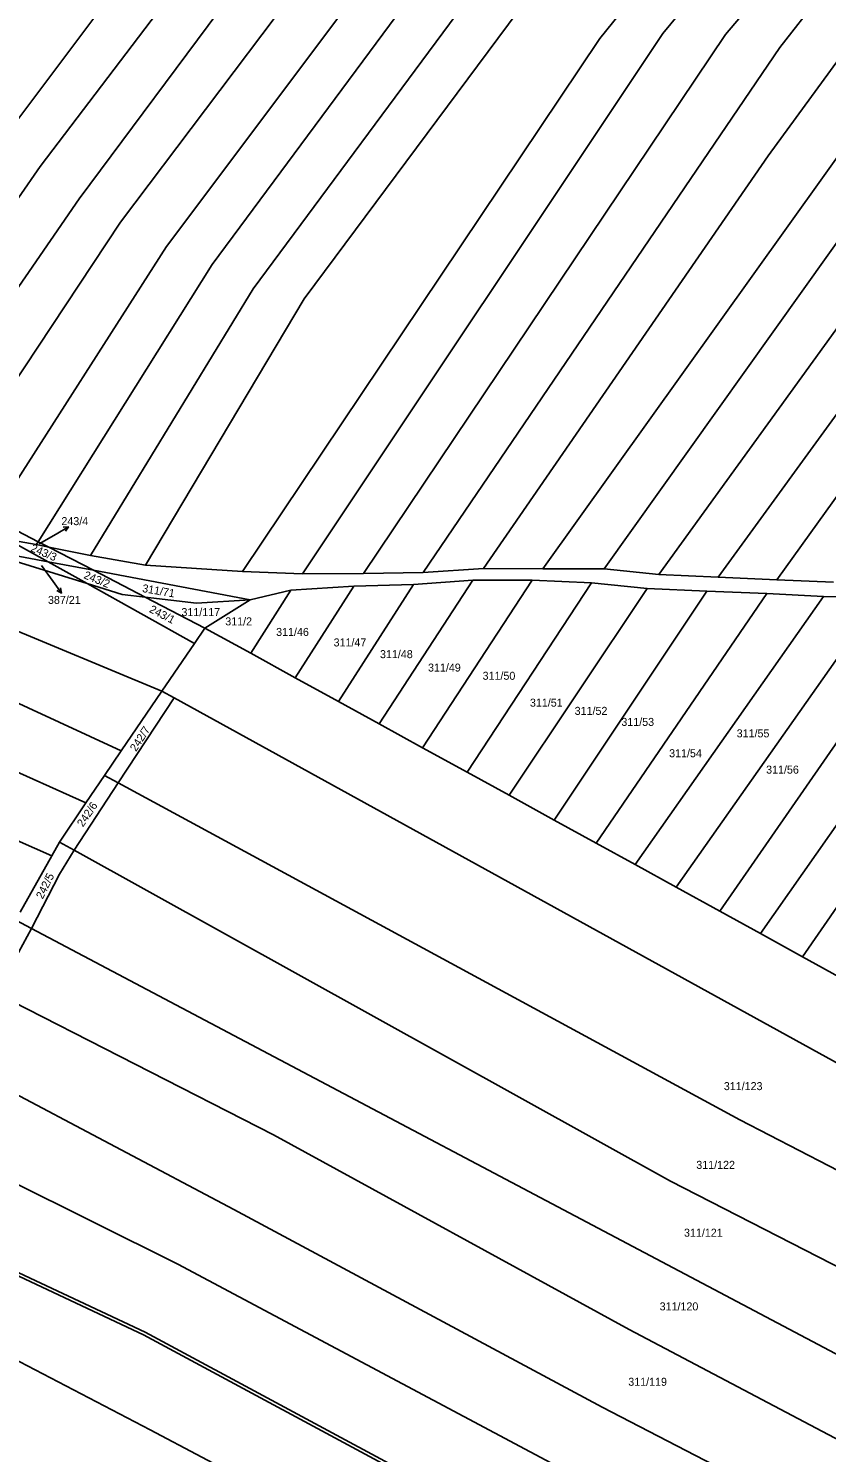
# Model space of a CAD drawing. Extents: x -580630 to -576196, y -1189024 to -1183567.
# Drawn here: x -579840 to -579670.5, y -1186458.9 to -1186156.5 of the extents above; entities that cross this region are included whole.
import ezdxf

# ---------------------------------------------------------------- set-up
doc = ezdxf.new("R2010")
doc.units = 0
for name, color, linetype in [('Vrstva 1', 7, 'Continuous'), ('Vrstva 16', 7, 'Continuous'), ('Vrstva 18', 7, 'Continuous'), ('Vrstva 6', 7, 'Continuous')]:
    doc.layers.add(name, color=color, linetype=linetype)

msp = doc.modelspace()

# ---------------------------------------------------------------- linework, layer by layer
at = {"layer": 'Vrstva 1'}
for p, q in [((-579847.64, -1186260.48), (-579837.97, -1186265.49)), ((-579844.38, -1186265.03), (-579835.86, -1186269.77)), ((-579837.97, -1186265.49), (-579835.72, -1186266.66)), ((-579835.72, -1186266.66), (-579826.23, -1186271.57)), ((-579835.86, -1186269.77), (-579827.55, -1186274.4)), ((-579826.23, -1186271.57), (-579815.23, -1186277.27)), ((-579827.55, -1186274.4), (-579804.76, -1186287.09)), ((-579815.23, -1186277.27), (-579802.55, -1186283.84)), ((-579802.55, -1186283.84), (-579804.76, -1186287.09)), ((-579802.55, -1186283.84), (-579792.82, -1186289.19)), ((-579804.76, -1186287.09), (-579811.7, -1186297.26)), ((-579792.82, -1186289.19), (-579783.36, -1186294.39)), ((-579820.34, -1186309.91), (-579811.7, -1186297.26)), ((-579811.7, -1186297.26), (-579809.11, -1186298.69)), ((-579783.36, -1186294.39), (-579774.18, -1186299.44)), ((-579809.11, -1186298.69), (-579820.97, -1186316.73)), ((-579809.11, -1186298.69), (-579630.91, -1186396.85)), ((-579774.18, -1186299.44), (-579765.52, -1186304.21)), ((-579765.52, -1186304.21), (-579756.35, -1186309.24)), ((-579756.35, -1186309.24), (-579746.87, -1186314.45)), ((-579823.91, -1186315.14), (-579820.34, -1186309.91)), ((-579823.91, -1186315.14), (-579827.82, -1186320.97)), ((-579746.87, -1186314.45), (-579737.97, -1186319.35)), ((-579820.97, -1186316.73), (-579830.35, -1186331.01)), ((-579827.82, -1186320.97), (-579833.42, -1186329.3)), ((-579737.97, -1186319.35), (-579728.36, -1186324.64)), ((-579728.36, -1186324.64), (-579719.49, -1186329.52)), ((-579833.42, -1186329.3), (-579835.05, -1186332.19)), ((-579719.49, -1186329.52), (-579711.2, -1186334.07)), ((-579835.05, -1186332.19), (-579841.79, -1186344.16)), ((-579830.35, -1186331.01), (-579833.41, -1186336.14)), ((-579833.41, -1186336.14), (-579839.4, -1186347.64)), ((-579711.2, -1186334.07), (-579702.5, -1186338.85)), ((-579702.5, -1186338.85), (-579693.22, -1186343.96)), ((-579693.22, -1186343.96), (-579684.59, -1186348.7)), ((-579839.4, -1186347.64), (-579846.88, -1186361.39)), ((-579684.59, -1186348.7), (-579675.63, -1186353.63)), ((-579675.63, -1186353.63), (-579666.49, -1186358.66)), ((-579808.31, -1186418.94), (-579844.26, -1186401)), ((-579851.95, -1186416.9), (-579815.57, -1186433.93)), ((-579815.26, -1186433.34), (-579851.66, -1186416.29)), ((-579705.84, -1186473.49), (-579808.31, -1186418.94)), ((-579814.2, -1186454.11), (-579875.68, -1186422.09)), ((-579713, -1186488.35), (-579815.26, -1186433.34)), ((-579815.57, -1186433.93), (-579713.31, -1186488.94)), ((-579574.05, -1186580.71), (-579814.2, -1186454.11))]:
    msp.add_line(p, q, dxfattribs=at)
at = {"layer": 'Vrstva 16'}
for p, q in [((-579837.73, -1186265.96), (-579834.14, -1186263.87)), ((-579831.549, -1186262.357), (-579834.14, -1186263.87)), ((-579837.29, -1186270.52), (-579834.78, -1186273.97)), ((-579833.019, -1186276.399), (-579834.78, -1186273.97))]:
    msp.add_line(p, q, dxfattribs=at)
for points in [[(-579832.665, -1186262.43), (-579831.549, -1186262.357), (-579832.161, -1186263.293)], [(-579833.201, -1186275.296), (-579833.019, -1186276.399), (-579834.011, -1186275.883)]]:
    msp.add_lwpolyline(points, dxfattribs=at)
at = {"layer": 'Vrstva 6'}
for p, q in [((-579698.35, -1186035.51), (-579820.47, -1186197.65)), ((-579684.37, -1186034.27), (-579810.73, -1186202.79)), ((-579800.99, -1186206.61), (-579678.58, -1186041.14)), ((-579665.61, -1186040.8), (-579792.31, -1186211.79)), ((-579781.49, -1186213.94), (-579655.46, -1186044.29)), ((-579718.69, -1186158.64), (-579662.82, -1186089.13)), ((-579781.38, -1186094.44), (-579844.63, -1186178.95)), ((-579692.01, -1186157.76), (-579638.14, -1186094.24)), ((-579705.34, -1186157.59), (-579656.08, -1186097.99)), ((-579773.91, -1186102.02), (-579837.52, -1186185.78)), ((-579760.81, -1186100.77), (-579829.29, -1186192.65)), ((-579664.24, -1186139.69), (-579680.45, -1186160.53)), ((-579781.8, -1186272.32), (-579705.34, -1186157.59)), ((-579768.89, -1186272.23), (-579692.01, -1186157.76)), ((-579682.94, -1186183.55), (-579663.49, -1186156.89)), ((-579794.56, -1186271.85), (-579718.69, -1186158.64)), ((-579680.45, -1186160.53), (-579756.18, -1186272.07)), ((-579662.19, -1186175.3), (-579730.78, -1186271.27)), ((-579717.8, -1186271.24), (-579653.94, -1186181.7)), ((-579640.18, -1186181.21), (-579706.15, -1186272.49)), ((-579743.36, -1186271.21), (-579682.94, -1186183.55)), ((-579837.52, -1186185.78), (-579877.74, -1186243.66)), ((-579632.33, -1186188.71), (-579693.54, -1186273.04)), ((-579829.29, -1186192.65), (-579868.15, -1186249.09)), ((-579820.47, -1186197.65), (-579858.26, -1186254.69)), ((-579810.73, -1186202.79), (-579847.64, -1186260.48)), ((-579681.09, -1186273.58), (-579629.3, -1186201.42)), ((-579837.97, -1186265.49), (-579800.99, -1186206.61)), ((-579792.31, -1186211.79), (-579826.89, -1186268.44)), ((-579815.19, -1186270.5), (-579781.49, -1186213.94)), ((-579835.86, -1186269.77), (-579852.59, -1186266.64)), ((-579852.59, -1186266.64), (-579827.55, -1186274.4)), ((-579844.38, -1186265.03), (-579838.37, -1186266.12)), ((-579838.37, -1186266.12), (-579837.97, -1186265.49)), ((-579835.72, -1186266.66), (-579838.37, -1186266.12)), ((-579826.89, -1186268.44), (-579835.72, -1186266.66)), ((-579826.23, -1186271.57), (-579835.86, -1186269.77)), ((-579826.89, -1186268.44), (-579815.19, -1186270.5)), ((-579792.95, -1186277.81), (-579826.23, -1186271.57)), ((-579815.19, -1186270.5), (-579794.56, -1186271.85)), ((-579794.56, -1186271.85), (-579781.8, -1186272.32)), ((-579781.8, -1186272.32), (-579768.89, -1186272.23)), ((-579756.18, -1186272.07), (-579768.89, -1186272.23)), ((-579756.18, -1186272.07), (-579743.36, -1186271.21)), ((-579730.78, -1186271.27), (-579743.36, -1186271.21)), ((-579730.78, -1186271.27), (-579717.8, -1186271.24)), ((-579706.15, -1186272.49), (-579717.8, -1186271.24)), ((-579706.15, -1186272.49), (-579693.54, -1186273.04)), ((-579693.54, -1186273.04), (-579681.09, -1186273.58)), ((-579827.55, -1186274.4), (-579820.15, -1186276.69)), ((-579792.95, -1186277.81), (-579784.33, -1186275.81)), ((-579792.82, -1186289.19), (-579784.33, -1186275.81)), ((-579784.33, -1186275.81), (-579770.9, -1186274.94)), ((-579783.36, -1186294.39), (-579770.9, -1186274.94)), ((-579774.18, -1186299.44), (-579758.29, -1186274.56)), ((-579770.9, -1186274.94), (-579758.29, -1186274.56)), ((-579765.52, -1186304.21), (-579745.67, -1186273.69)), ((-579758.29, -1186274.56), (-579745.67, -1186273.69)), ((-579756.35, -1186309.24), (-579733.06, -1186273.69)), ((-579746.87, -1186314.45), (-579720.44, -1186274.25)), ((-579745.67, -1186273.69), (-579733.06, -1186273.69)), ((-579737.97, -1186319.35), (-579708.66, -1186275.41)), ((-579733.06, -1186273.69), (-579720.44, -1186274.25)), ((-579728.36, -1186324.64), (-579695.98, -1186276.02)), ((-579720.44, -1186274.25), (-579708.66, -1186275.41)), ((-579708.66, -1186275.41), (-579695.98, -1186276.02)), ((-579695.98, -1186276.02), (-579683.2, -1186276.49)), ((-579681.09, -1186273.58), (-579669.06, -1186274.11)), ((-579861.65, -1186276.47), (-579811.7, -1186297.26)), ((-579820.15, -1186276.69), (-579815.23, -1186277.27)), ((-579815.23, -1186277.27), (-579804.32, -1186278.56)), ((-579804.32, -1186278.56), (-579792.95, -1186277.81)), ((-579802.55, -1186283.84), (-579792.95, -1186277.81)), ((-579719.49, -1186329.52), (-579683.2, -1186276.49)), ((-579711.2, -1186334.07), (-579671.21, -1186277.14)), ((-579702.5, -1186338.85), (-579659.27, -1186277.41)), ((-579693.22, -1186343.96), (-579647.47, -1186277.92)), ((-579683.2, -1186276.49), (-579671.21, -1186277.14)), ((-579671.21, -1186277.14), (-579659.27, -1186277.41)), ((-579878.14, -1186283.3), (-579820.34, -1186309.91)), ((-579939.43, -1186286.38), (-579835.05, -1186332.19)), ((-579884.5, -1186295.46), (-579827.82, -1186320.97)), ((-579823.91, -1186315.14), (-579820.97, -1186316.73)), ((-579675.63, -1186353.63), (-579648.12, -1186313.69)), ((-579820.97, -1186316.73), (-579688.97, -1186388.29)), ((-579684.59, -1186348.7), (-579661.85, -1186316.29)), ((-579830.35, -1186331.01), (-579833.42, -1186329.3)), ((-579703.71, -1186401.29), (-579830.35, -1186331.01)), ((-579842.75, -1186345.87), (-579839.4, -1186347.64)), ((-579839.4, -1186347.64), (-579528.18, -1186512.31)), ((-579788, -1186391.47), (-579846.88, -1186361.39)), ((-579854.1, -1186376.82), (-579796.41, -1186407.35)), ((-579688.97, -1186388.29), (-579589.05, -1186440.04)), ((-579712.48, -1186432.8), (-579788, -1186391.47)), ((-579605.54, -1186451.66), (-579703.71, -1186401.29)), ((-579796.41, -1186407.35), (-579718.2, -1186449.29)), ((-579568.19, -1186508.91), (-579712.48, -1186432.8)), ((-579718.2, -1186449.29), (-579575.66, -1186523.03))]:
    msp.add_line(p, q, dxfattribs=at)

# ---------------------------------------------------------------- texts
at = {"layer": 'Vrstva 16'}
for s, p in [('243/4', (-579833.044, -1186261.98)), ('387/21', (-579835.892, -1186278.71))]:
    msp.add_text(s, height=1.7, dxfattribs=at).set_placement(p)
at = {"layer": 'Vrstva 18'}
for s, rotation, p in [('243/3', 337.07107, (-579839.72, -1186267.466)), ('243/2', 337.81592, (-579828.436, -1186273.215)), ('311/71', 350.19181, (-579815.97, -1186276.168)), ('243/1', 332.6593, (-579814.523, -1186280.379)), ('242/7', 57.18119, (-579817.189, -1186310.195)), ('242/6', 55.80609, (-579828.462, -1186326.212)), ('242/5', 63.7702, (-579837.013, -1186341.514))]:
    msp.add_text(s, height=1.7, rotation=rotation, dxfattribs=at).set_placement(p)
for s, height, p in [('243/4', 0.1, (-579837.941, -1186265.96)), ('387/21', 0.1, (-579837.521, -1186270.52)), ('311/117', 1.7, (-579807.547, -1186281.3)), ('311/2', 1.7, (-579798.238, -1186283.27)), ('311/46', 1.7, (-579787.433, -1186285.51)), ('311/47', 1.7, (-579775.233, -1186287.74)), ('311/48', 1.7, (-579765.374, -1186290.23)), ('311/49', 1.7, (-579755.173, -1186293.08)), ('311/50', 1.7, (-579743.587, -1186294.82)), ('311/51', 1.7, (-579733.532, -1186300.53)), ('311/52', 1.7, (-579724.034, -1186302.27)), ('311/53', 1.7, (-579714.117, -1186304.62)), ('311/55', 1.7, (-579689.627, -1186307.05)), ('311/54', 1.7, (-579703.97, -1186311.27)), ('311/56', 1.7, (-579683.37, -1186314.75)), ('311/123', 1.7, (-579692.355, -1186381.97)), ('311/122', 1.7, (-579698.202, -1186398.69)), ('311/121', 1.7, (-579700.81, -1186413.1)), ('311/120', 1.7, (-579705.985, -1186428.75)), ('311/119', 1.7, (-579712.647, -1186444.76))]:
    msp.add_text(s, height=height, dxfattribs=at).set_placement(p)

doc.saveas('drawing.dxf')
